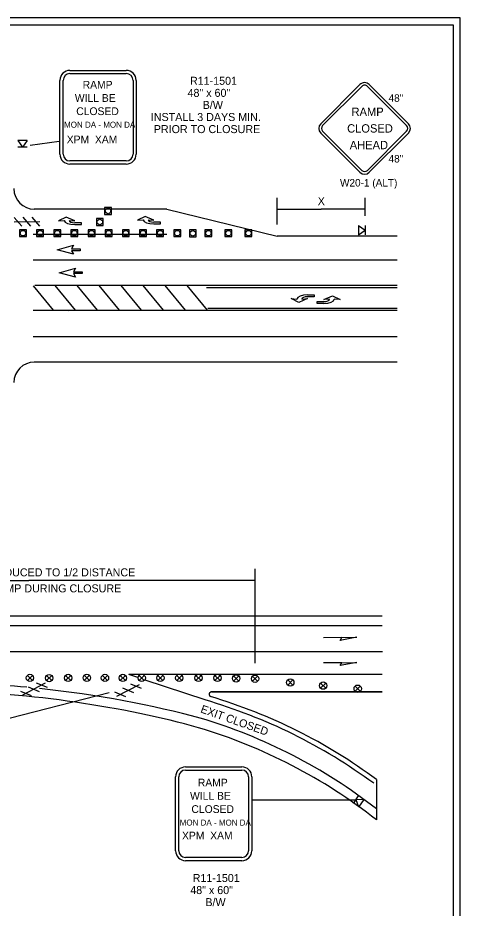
# Model space of a CAD drawing. Extents: x 99988 to 100172, y 99995 to 100047.
# Drawn here: x 100011.94 to 100015.81, y 100002.65 to 100010.44 of the extents above; entities that cross this region are included whole.
import ezdxf

# ---------------------------------------------------------------- set-up
doc = ezdxf.new("R2010")
doc.units = 0
for name, color, linetype in [('Default', 7, 'Continuous'), ('Level 15', 7, 'Continuous'), ('Level 20', 7, 'Continuous'), ('RD_MK_TrafficArrowType1SNew', 7, 'Continuous'), ('RD_MK_TrafficArrowType2LNew', 7, 'Continuous'), ('RD_MK_TrafficArrowType2RNew', 7, 'Continuous'), ('SH_DE_DetailBody1Text', 7, 'Continuous'), ('SH_GI_PlotLimits', 7, 'Continuous'), ('SH_GI_SheetBorder', 7, 'Continuous'), ('SH_GI_TrafficMvmntArrowRt1Lane', 7, 'Continuous'), ('TR_SN_RegulatorySigns', 7, 'Continuous'), ('TR_SN_WarningSigns', 7, 'Continuous'), ('TR_WZ_BarricadeType3', 7, 'Continuous'), ('TR_WZ_TrafficSafetyCone', 7, 'Continuous'), ('TR_WZ_WorkZoneDetails', 7, 'Continuous')]:
    doc.layers.add(name, color=color, linetype=linetype)

msp = doc.modelspace()

# ---------------------------------------------------------------- linework, layer by layer
at = {"layer": 'Default'}
for p, q in [((100011.9428, 100009.365), (100011.9831, 100009.3072)), ((100012.0233, 100009.365), (100011.9428, 100009.365)), ((100012.0233, 100009.365), (100011.9831, 100009.3072)), ((100012.0233, 100009.3072), (100011.9428, 100009.3072)), ((100014.9236, 100008.6208), (100014.9813, 100008.5807)), ((100014.9236, 100008.6208), (100014.9236, 100008.5404)), ((100014.9813, 100008.6208), (100014.9813, 100008.5404)), ((100014.9236, 100008.5404), (100014.9813, 100008.5807)), ((100004.2658, 100004.8971), (100015.1319, 100004.8971)), ((100012.0711, 100004.6441), (100012.0258, 100004.6893)), ((100012.0711, 100004.6893), (100012.0258, 100004.6441)), ((100012.2397, 100004.6431), (100012.1945, 100004.6883)), ((100012.2397, 100004.6883), (100012.1945, 100004.6431)), ((100012.406, 100004.6441), (100012.3608, 100004.6893)), ((100012.406, 100004.6893), (100012.3608, 100004.6441)), ((100012.5685, 100004.6446), (100012.5233, 100004.6898)), ((100012.5685, 100004.6898), (100012.5233, 100004.6446)), ((100012.7276, 100004.6441), (100012.6823, 100004.6893)), ((100012.7276, 100004.6893), (100012.6823, 100004.6441)), ((100012.8832, 100004.6441), (100012.8379, 100004.6893)), ((100012.8832, 100004.6893), (100012.8379, 100004.6441)), ((100012.9934, 100004.6695), (100012.9135, 100004.6961)), ((100013.0492, 100004.6441), (100013.0039, 100004.6893)), ((100013.0492, 100004.6893), (100013.0039, 100004.6441)), ((100013.2124, 100004.6441), (100013.1671, 100004.6893)), ((100013.2124, 100004.6893), (100013.1671, 100004.6441)), ((100013.3774, 100004.6441), (100013.3322, 100004.6893)), ((100013.3774, 100004.6893), (100013.3322, 100004.6441)), ((100013.5456, 100004.6439), (100013.5004, 100004.6892)), ((100013.5456, 100004.6892), (100013.5004, 100004.6439)), ((100013.7124, 100004.6441), (100013.6671, 100004.6893)), ((100013.7124, 100004.6893), (100013.6671, 100004.6441)), ((100013.8749, 100004.6399), (100013.8297, 100004.6851)), ((100013.8749, 100004.6851), (100013.8297, 100004.6399)), ((100014.0406, 100004.6374), (100013.9954, 100004.6826)), ((100014.0406, 100004.6826), (100013.9954, 100004.6374)), ((100013.5803, 100004.4745), (100013.0573, 100004.6483)), ((100014.3488, 100004.6038), (100014.3035, 100004.6491)), ((100014.3488, 100004.6491), (100014.3035, 100004.6038)), ((100014.6366, 100004.5768), (100014.5914, 100004.6221)), ((100014.6366, 100004.6221), (100014.5914, 100004.5768)), ((100014.9383, 100004.5502), (100014.893, 100004.5954)), ((100014.9383, 100004.5954), (100014.893, 100004.5502)), ((100014.8788, 100003.5685), (100014.9234, 100003.6354)), ((100014.9715, 100003.6034), (100014.9011, 100003.6019)), ((100014.9269, 100003.5365), (100014.9011, 100003.6019)), ((100014.9269, 100003.5365), (100014.9715, 100003.6034))]:
    msp.add_line(p, q, dxfattribs=at)
for centre in [(100012.0485, 100004.6667), (100012.2171, 100004.6657), (100012.3834, 100004.6667), (100012.5459, 100004.6672), (100012.705, 100004.6667), (100012.8606, 100004.6667), (100013.0265, 100004.6667), (100013.1897, 100004.6667), (100013.3548, 100004.6667), (100013.523, 100004.6666), (100013.6897, 100004.6667), (100013.8523, 100004.6625), (100014.018, 100004.66), (100014.3262, 100004.6264), (100014.614, 100004.5994), (100014.9157, 100004.5728)]:
    msp.add_circle(centre, 0.032, dxfattribs=at)
at = {"layer": 'Level 15'}
for p, q in [((100014.2106, 100008.7644), (100014.5958, 100008.7644)), ((100014.9811, 100008.7644), (100014.5958, 100008.7644)), ((100010.0571, 100005.5197), (100012.0375, 100005.5197)), ((100014.018, 100005.5197), (100012.0375, 100005.5197))]:
    msp.add_line(p, q, dxfattribs=at)
at = {"layer": 'RD_MK_TrafficArrowType1SNew'}
for points in [[(100012.487, 100008.4014), (100012.412, 100008.4014), (100012.4287, 100008.3702), (100012.287, 100008.4098), (100012.4287, 100008.4493), (100012.412, 100008.4181), (100012.487, 100008.4181)], [(100012.5045, 100008.2009), (100012.4295, 100008.2009), (100012.4461, 100008.1697), (100012.3045, 100008.2093), (100012.4461, 100008.2489), (100012.4295, 100008.2176), (100012.5045, 100008.2176)]]:
    msp.add_lwpolyline(points, close=True, dxfattribs=at)
at = {"layer": 'RD_MK_TrafficArrowType2LNew'}
for p, q in [((100014.4763, 100008.016), (100014.4763, 100008.016)), ((100014.4763, 100008.016), (100014.4763, 100008.016)), ((100014.4763, 100007.9993), (100014.4763, 100007.9993)), ((100014.3847, 100007.9785), (100014.3847, 100007.9785)), ((100014.4263, 100007.9785), (100014.4263, 100007.9785)), ((100014.6195, 100007.9573), (100014.6195, 100007.9573)), ((100014.6195, 100007.9406), (100014.6195, 100007.9406)), ((100014.6196, 100007.9406), (100014.6195, 100007.9406)), ((100014.6695, 100007.9781), (100014.6695, 100007.9781)), ((100014.7112, 100007.9781), (100014.7112, 100007.9781))]:
    msp.add_line(p, q, dxfattribs=at)
for points in [[(100014.4763, 100008.016), (100014.5347, 100008.016), (100014.5347, 100007.9993), (100014.4763, 100007.9993)], [(100014.6695, 100007.9781), (100014.6195, 100007.9739), (100014.6945, 100008.0073), (100014.7612, 100007.9739), (100014.7112, 100007.9781)], [(100014.4263, 100007.9785), (100014.4763, 100007.9827), (100014.4013, 100007.9493), (100014.3347, 100007.9827), (100014.3847, 100007.9785)], [(100014.6195, 100007.9406), (100014.5612, 100007.9406), (100014.5612, 100007.9573), (100014.6195, 100007.9573)]]:
    msp.add_lwpolyline(points, dxfattribs=at)
for centre, major_axis, ratio, start_param in [((100014.4763, 100007.9785), (-0.0917, 0), 0.40879, 4.712524), ((100014.4763, 100007.9785), (-0.05, 0), 0.41611, 4.712518), ((100014.6195, 100007.9781), (0.05, 0), 0.41611, 4.712518), ((100014.6195, 100007.9781), (0.0917, 0), 0.40879, 4.712524)]:
    msp.add_ellipse(centre, major_axis=major_axis, ratio=ratio, start_param=start_param, end_param=6.283185, dxfattribs=at)
at = {"layer": 'RD_MK_TrafficArrowType2RNew'}
for p, q in [((100012.4406, 100008.6295), (100012.4406, 100008.6294)), ((100013.1321, 100008.6352), (100013.1321, 100008.6352))]:
    msp.add_line(p, q, dxfattribs=at)
for points in [[(100013.0821, 100008.6726), (100013.1321, 100008.6685), (100013.0571, 100008.7018), (100012.9904, 100008.6685), (100013.0404, 100008.6726)], [(100012.3906, 100008.6669), (100012.4406, 100008.6628), (100012.3656, 100008.6961), (100012.2989, 100008.6628), (100012.3489, 100008.6669)], [(100012.4406, 100008.6294), (100012.4989, 100008.6294), (100012.4989, 100008.6461), (100012.4406, 100008.6461)], [(100013.1321, 100008.6352), (100013.1904, 100008.6352), (100013.1904, 100008.6518), (100013.1321, 100008.6518)]]:
    msp.add_lwpolyline(points, dxfattribs=at)
for centre, major_axis, ratio, end_param in [((100012.4406, 100008.6669), (-0.0917, 0), 0.40879, 1.570662), ((100012.4406, 100008.6669), (-0.05, 0), 0.41611, 1.570668), ((100013.1321, 100008.6726), (-0.0917, 0), 0.40879, 1.570662), ((100013.1321, 100008.6726), (-0.05, 0), 0.41611, 1.570668)]:
    msp.add_ellipse(centre, major_axis=major_axis, ratio=ratio, start_param=0, end_param=end_param, dxfattribs=at)
at = {"layer": 'SH_GI_PlotLimits'}
msp.add_lwpolyline([(99999.3125, 99999.9375), (100015.8125, 99999.9375), (100015.8125, 100010.4375), (99999.3125, 100010.4375)], close=True, dxfattribs=at)
at = {"layer": 'SH_GI_SheetBorder'}
for p, q in [((100000, 100010.375), (100015.75, 100010.375)), ((100015.75, 100010.375), (100015.75, 100000))]:
    msp.add_line(p, q, dxfattribs=at)
at = {"layer": 'SH_GI_TrafficMvmntArrowRt1Lane'}
for p, q in [((100014.778, 100005.0206), (100014.6173, 100005.0184)), ((100014.778, 100004.8001), (100014.6173, 100004.798))]:
    msp.add_line(p, q, dxfattribs=at)
for points in [[(100014.909, 100005.0223), (100014.7635, 100004.9947), (100014.778, 100005.0206)], [(100014.909, 100004.8018), (100014.7635, 100004.7742), (100014.778, 100004.8001)]]:
    msp.add_lwpolyline(points, close=True, dxfattribs=at)
at = {"layer": 'TR_SN_RegulatorySigns'}
for p, q in [((100012.3985, 100009.9783), (100012.8907, 100009.9783)), ((100012.3111, 100009.2459), (100012.3111, 100009.8909)), ((100012.9782, 100009.8909), (100012.9782, 100009.2459)), ((100012.8907, 100009.1584), (100012.3985, 100009.1584)), ((100013.41, 100003.8891), (100013.9023, 100003.8891)), ((100013.3226, 100003.1567), (100013.3226, 100003.8017)), ((100013.9897, 100003.8017), (100013.9897, 100003.1567)), ((100013.9023, 100003.0692), (100013.41, 100003.0692))]:
    msp.add_line(p, q, dxfattribs=at)
for points in [[(100012.3985, 100009.9503), (100012.8907, 100009.9503)], [(100012.3391, 100009.2459), (100012.3391, 100009.8909)], [(100012.9501, 100009.8909), (100012.9501, 100009.2459)], [(100012.8907, 100009.1865), (100012.3985, 100009.1865)], [(100013.3506, 100003.1567), (100013.3506, 100003.8017)], [(100013.41, 100003.8611), (100013.9023, 100003.8611)], [(100013.9617, 100003.8017), (100013.9617, 100003.1567)], [(100013.9023, 100003.0973), (100013.41, 100003.0973)]]:
    msp.add_lwpolyline(points, dxfattribs=at)
for centre, radius, start, end in [((100012.3985, 100009.8909), 0.0874, 90, 180), ((100012.3985, 100009.8909), 0.0594, 90, 180), ((100012.8907, 100009.8909), 0.0874, 0, 90), ((100012.8907, 100009.8909), 0.0594, 0, 90), ((100012.3985, 100009.2459), 0.0874, 180, 270), ((100012.3985, 100009.2459), 0.0594, 180, 270), ((100012.8907, 100009.2459), 0.0594, 270, 0), ((100012.8907, 100009.2459), 0.0874, 270, 0), ((100013.41, 100003.8017), 0.0874, 90, 180), ((100013.9023, 100003.8017), 0.0874, 0, 90), ((100013.41, 100003.8017), 0.0594, 90, 180), ((100013.9023, 100003.8017), 0.0594, 0, 90), ((100013.41, 100003.1567), 0.0874, 180, 270), ((100013.41, 100003.1567), 0.0594, 180, 270), ((100013.9023, 100003.1567), 0.0594, 270, 0), ((100013.9023, 100003.1567), 0.0874, 270, 0)]:
    msp.add_arc(centre, radius, start, end, dxfattribs=at)
at = {"layer": 'TR_SN_WarningSigns'}
for p, q in [((100014.5924, 100009.5116), (100014.9351, 100009.8542)), ((100014.6087, 100009.4952), (100014.9514, 100009.8379)), ((100015.0004, 100009.8379), (100015.3431, 100009.4952)), ((100015.0167, 100009.8542), (100015.3594, 100009.5116)), ((100014.9351, 100009.0873), (100014.5924, 100009.43)), ((100014.9514, 100009.1036), (100014.6087, 100009.4463)), ((100015.3431, 100009.4463), (100015.0004, 100009.1036)), ((100015.3594, 100009.43), (100015.0167, 100009.0873))]:
    msp.add_line(p, q, dxfattribs=at)
for centre, radius, start, end in [((100014.9759, 100009.8134), 0.0577, 44.99628, 134.99965), ((100014.9759, 100009.8134), 0.0346, 44.99628, 134.99965), ((100014.6332, 100009.4708), 0.0577, 134.99658, 224.99358), ((100014.6332, 100009.4708), 0.0346, 134.99658, 224.99358), ((100015.3186, 100009.4708), 0.0346, 314.99936, 44.99485), ((100015.3186, 100009.4708), 0.0577, 314.99936, 44.99485), ((100014.9759, 100009.1281), 0.0577, 225, 314.99958), ((100014.9759, 100009.1281), 0.0346, 225, 314.99958)]:
    msp.add_arc(centre, radius, start, end, dxfattribs=at)
at = {"layer": 'TR_WZ_BarricadeType3'}
for p, q in [((100011.9777, 100008.6146), (100011.91, 100008.6932)), ((100011.9104, 100008.6535), (100012.1342, 100008.6558)), ((100012.0562, 100008.6154), (100011.9885, 100008.694)), ((100012.1346, 100008.6162), (100012.067, 100008.6948)), ((100012.1813, 100004.6207), (100011.9831, 100004.5168)), ((100012.0342, 100004.5883), (100012.1302, 100004.5492)), ((100012.1037, 100004.6248), (100012.1997, 100004.5856)), ((100012.8087, 100004.5059), (100013.0076, 100004.6085)), ((100012.956, 100004.5373), (100012.8602, 100004.5771)), ((100013.0257, 100004.5732), (100012.93, 100004.6131)), ((100011.9647, 100004.5519), (100012.0607, 100004.5127)), ((100012.8862, 100004.5013), (100012.7905, 100004.5411))]:
    msp.add_line(p, q, dxfattribs=at)
at = {"layer": 'TR_WZ_TrafficSafetyCone'}
for points in [[(100012.7625, 100008.7193), (100012.7625, 100008.78), (100012.7018, 100008.78), (100012.7018, 100008.7193)], [(100012.6902, 100008.6219), (100012.6902, 100008.6826), (100012.6295, 100008.6826), (100012.6295, 100008.6219)], [(100012.0178, 100008.5246), (100012.0178, 100008.5853), (100011.9571, 100008.5853), (100011.9571, 100008.5246)], [(100012.1678, 100008.5246), (100012.1678, 100008.5853), (100012.1071, 100008.5853), (100012.1071, 100008.5246)], [(100012.3178, 100008.5246), (100012.3178, 100008.5853), (100012.2571, 100008.5853), (100012.2571, 100008.5246)], [(100012.4678, 100008.5246), (100012.4678, 100008.5853), (100012.4071, 100008.5853), (100012.4071, 100008.5246)], [(100012.6178, 100008.5246), (100012.6178, 100008.5853), (100012.5571, 100008.5853), (100012.5571, 100008.5246)], [(100012.7678, 100008.5246), (100012.7678, 100008.5853), (100012.7071, 100008.5853), (100012.7071, 100008.5246)], [(100012.9178, 100008.5246), (100012.9178, 100008.5853), (100012.8571, 100008.5853), (100012.8571, 100008.5246)], [(100013.0678, 100008.5246), (100013.0678, 100008.5853), (100013.0071, 100008.5853), (100013.0071, 100008.5246)], [(100013.2178, 100008.5246), (100013.2178, 100008.5853), (100013.1571, 100008.5853), (100013.1571, 100008.5246)], [(100013.3678, 100008.5246), (100013.3678, 100008.5853), (100013.3071, 100008.5853), (100013.3071, 100008.5246)], [(100013.5037, 100008.5228), (100013.5037, 100008.5835), (100013.443, 100008.5835), (100013.443, 100008.5228)], [(100013.6403, 100008.5246), (100013.6403, 100008.5853), (100013.5795, 100008.5853), (100013.5795, 100008.5246)], [(100013.8153, 100008.5246), (100013.8153, 100008.5853), (100013.7545, 100008.5853), (100013.7545, 100008.5246)], [(100013.9903, 100008.5246), (100013.9903, 100008.5853), (100013.9295, 100008.5853), (100013.9295, 100008.5246)]]:
    msp.add_lwpolyline(points, close=True, dxfattribs=at)
for centre in [(100012.7322, 100008.7497), (100012.6598, 100008.6523), (100011.9875, 100008.5549), (100012.1375, 100008.5549), (100012.2875, 100008.5549), (100012.4375, 100008.5549), (100012.5875, 100008.5549), (100012.7375, 100008.5549), (100012.8875, 100008.5549), (100013.0375, 100008.5549), (100013.1875, 100008.5549), (100013.3375, 100008.5549), (100013.4733, 100008.5532), (100013.6099, 100008.5549), (100013.7849, 100008.5549), (100013.9599, 100008.5549)]:
    msp.add_circle(centre, 0.0244, dxfattribs=at)
at = {"layer": 'TR_WZ_WorkZoneDetails'}
for p, q in [((100012.3037, 100009.3556), (100012.0517, 100009.32)), ((100014.2106, 100008.6292), (100014.2106, 100008.8644)), ((100014.9811, 100008.7074), (100014.9811, 100008.8644)), ((100013.2451, 100008.7652), (100012.0867, 100008.7652)), ((100013.2451, 100008.7652), (100014.2106, 100008.5292)), ((100013.245, 100008.5435), (100012.0778, 100008.5435)), ((100015.2612, 100008.5292), (100014.2106, 100008.5292)), ((100015.2612, 100008.32), (100012.0778, 100008.32)), ((100012.0778, 100008.0935), (100012.2518, 100007.8804)), ((100015.2612, 100008.0965), (100012.0927, 100008.0965)), ((100012.2677, 100008.0965), (100012.4442, 100007.8804)), ((100012.4601, 100008.0965), (100012.6366, 100007.8804)), ((100012.6525, 100008.0965), (100012.829, 100007.8804)), ((100012.8449, 100008.0965), (100013.0214, 100007.8804)), ((100013.0373, 100008.0965), (100013.2138, 100007.8804)), ((100013.2297, 100008.0965), (100013.4062, 100007.8804)), ((100013.4221, 100008.0965), (100013.5986, 100007.8804)), ((100015.2612, 100008.0765), (100013.5927, 100008.0765)), ((100012.0778, 100007.8804), (100015.2612, 100007.8804)), ((100012.3875, 100007.872), (100012.3877, 100007.8721)), ((100013.6054, 100007.9003), (100015.2612, 100007.9003)), ((100015.2612, 100007.6494), (100012.0778, 100007.6494)), ((100015.2612, 100007.4277), (100012.0867, 100007.4277)), ((100014.018, 100004.7966), (100014.018, 100005.6197)), ((100004.2658, 100005.2089), (100015.1308, 100005.2089)), ((100004.2658, 100005.1256), (100015.1308, 100005.1256)), ((100015.1308, 100004.6961), (100012.9135, 100004.6961)), ((100012.743, 100004.5355), (100011.5426, 100004.2296)), ((100015.1308, 100004.5463), (100013.6376, 100004.5456)), ((100013.6376, 100004.5463), (100015.1308, 100004.5463)), ((100015.0802, 100003.7785), (100015.0802, 100003.425)), ((100014.8945, 100003.5984), (100013.9897, 100003.5984))]:
    msp.add_line(p, q, dxfattribs=at)
for centre, radius, start, end in [((100012.0867, 100008.944), 0.1788, 180, 270), ((100012.0867, 100007.2489), 0.1788, 90, 180), ((100013.6376, 100004.5237), 0.0219, 90, 246.87648), ((100012.2997, 100000.0275), 4.6692, 53.45154, 73.45985), ((100012.252, 99999.9277), 4.7368, 53.70681, 73.71513), ((100012.2093, 99999.8393), 4.6692, 52.05728, 73.45985), ((100012.1934, 99999.7552), 4.6692, 51.80951, 73.45985)]:
    msp.add_arc(centre, radius, start, end, dxfattribs=at)
for centre, start_param, end_param in [((100012.4018, 100004.1565), 4.939264, 5.168134), ((100012.4018, 100004.1565), 4.10836, 4.879845), ((100012.3573, 100004.0823), 4.089543, 5.297244)]:
    msp.add_ellipse(centre, major_axis=(-1.9237, 0.2704), ratio=0.196247, start_param=start_param, end_param=end_param, dxfattribs=at)

# ---------------------------------------------------------------- texts
at = {"layer": 'Level 20'}
for s, p in [('X', (100014.5661, 100008.7994)), ('DEVICE SPACING REDUCED TO 1/2 DISTANCE', (100010.8734, 100005.5547))]:
    msp.add_text(s, height=0.07, rotation=360, dxfattribs=at).set_placement(p)
msp.add_text('ACROSS EXIT RAMP DURING CLOSURE', height=0.07, dxfattribs=at).set_placement((100011.0477, 100005.4147))
at = {"layer": 'SH_DE_DetailBody1Text'}
for s, p in [('R11-1501', (100013.4487, 100009.8519)), ('48" x 60"', (100013.4273, 100009.7463)), ('B/W', (100013.5598, 100009.6407)), ('INSTALL 3 DAYS MIN.', (100013.1062, 100009.5352)), ('PRIOR TO CLOSURE', (100013.1319, 100009.4296)), ('R11-1501', (100013.4724, 100002.8827)), ('48" x 60"', (100013.451, 100002.7772)), ('B/W', (100013.5834, 100002.6716))]:
    msp.add_text(s, height=0.07, dxfattribs=at).set_placement(p)
msp.add_text('EXIT CLOSED', height=0.07, rotation=340.5147, dxfattribs=at).set_placement((100013.5354, 100004.3669))
at = {"layer": 'TR_SN_RegulatorySigns'}
for s, height, p in [('RAMP', 0.06769, (100012.5098, 100009.8186)), ('WILL BE', 0.06769, (100012.4415, 100009.7029)), ('CLOSED', 0.06769, (100012.4536, 100009.5871)), ('MON DA - MON DA', 0.052375, (100012.3472, 100009.4768)), ('XPM  XAM', 0.06769, (100012.3705, 100009.34)), ('RAMP', 0.06769, (100013.5173, 100003.718)), ('WILL BE', 0.06769, (100013.4491, 100003.6022)), ('CLOSED', 0.06769, (100013.4611, 100003.4865)), ('MON DA - MON DA', 0.052375, (100013.3587, 100003.3762)), ('XPM  XAM', 0.06769, (100013.3789, 100003.255))]:
    msp.add_text(s, height=height, dxfattribs=at).set_placement(p)
at = {"layer": 'TR_SN_WarningSigns'}
for s, height, p in [('48"', 0.06563, (100015.1856, 100009.7031)), ('RAMP', 0.07268, (100014.8619, 100009.5798)), ('CLOSED', 0.07268, (100014.8234, 100009.4344)), ('AHEAD', 0.07268, (100014.8462, 100009.2891)), ('48"', 0.06563, (100015.1856, 100009.1728)), ('W20-1 (ALT)', 0.065625, (100014.7608, 100008.9626))]:
    msp.add_text(s, height=height, dxfattribs=at).set_placement(p)

doc.saveas('drawing.dxf')
